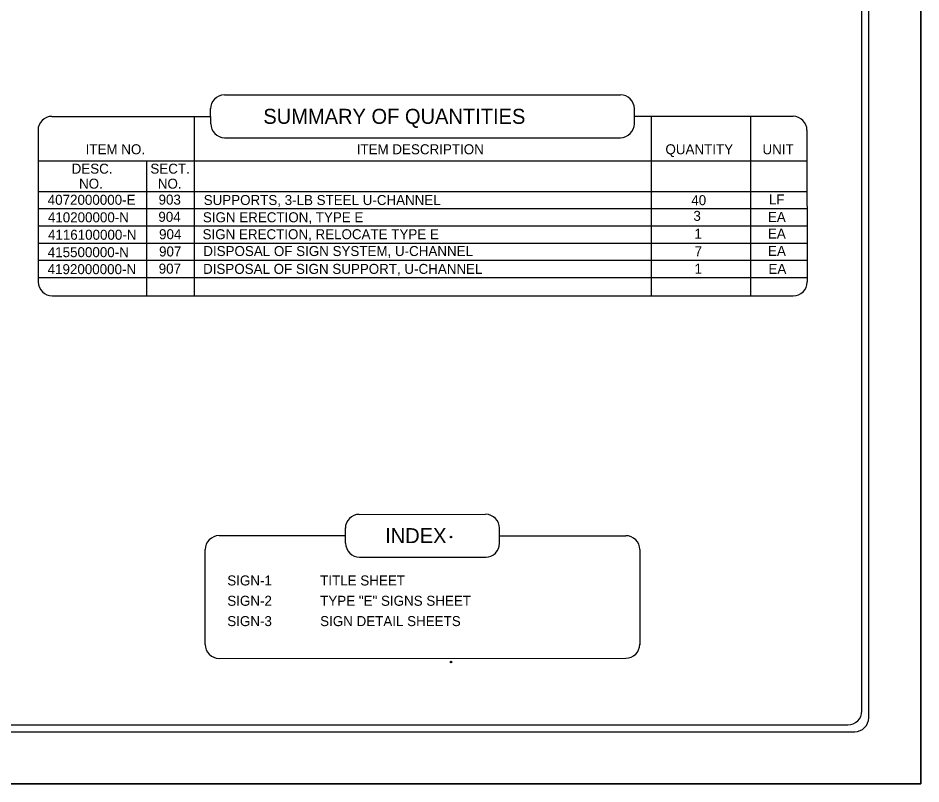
# Model space of a CAD drawing. Extents: x 1359317 to 1361345, y 1001522 to 1002524.
# Drawn here: x 1360274 to 1360865, y 1001522 to 1002023 of the extents above; entities that cross this region are included whole.
import ezdxf

# ---------------------------------------------------------------- set-up
doc = ezdxf.new("R2010")
doc.units = 0
for name, color, linetype in [('Default', 7, 'Continuous'), ('Draft_Construction', 7, 'Continuous'), ('Sheet Plot Border Outside CELL', 7, 'Continuous'), ('Sheet_Title_CELL', 7, 'Continuous'), ('Text', 7, 'Continuous'), ('z - Construction', 7, 'Continuous')]:
    doc.layers.add(name, color=color, linetype=linetype)

msp = doc.modelspace()

# ---------------------------------------------------------------- linework, layer by layer
at = {"layer": 'Default'}
for p, q in [((1360389.57, 1001958.51), (1360389.57, 1001841.1)), ((1360688.47, 1001958.52), (1360688.47, 1001841.09)), ((1360753.47, 1001958.52), (1360753.47, 1001841.09)), ((1360753.47, 1001949.44), (1360753.47, 1001929.44)), ((1360287.54, 1001929.38), (1360790.47, 1001929.45)), ((1360358.55, 1001929.39), (1360358.55, 1001841.11)), ((1360753.47, 1001929.44), (1360790.47, 1001929.45)), ((1360287.57, 1001909.39), (1360790.48, 1001909.39)), ((1360287.57, 1001898.15), (1360790.48, 1001898.15)), ((1360287.57, 1001886.91), (1360790.48, 1001886.91)), ((1360287.57, 1001875.66), (1360790.48, 1001875.66)), ((1360287.57, 1001864.42), (1360790.48, 1001864.42)), ((1360287.57, 1001853.17), (1360790.48, 1001853.17))]:
    msp.add_line(p, q, dxfattribs=at)
at = {"layer": 'Draft_Construction'}
for centre in [(1360557.61, 1001683.35), (1360557.61, 1001601.63)]:
    msp.add_circle(centre, 0.546, dxfattribs=at)
at = {"layer": 'Sheet Plot Border Outside CELL'}
msp.add_lwpolyline([(1359316.74, 1002523.7), (1360865.01, 1002523.7), (1360865.01, 1001521.88), (1359316.74, 1001521.88)], close=True, dxfattribs=at)
at = {"layer": 'Sheet_Title_CELL'}
for p, q in [((1360826.3, 1001569.62), (1360826.3, 1002475.82)), ((1360830.86, 1001565.14), (1360830.86, 1002480.44)), ((1360409.38, 1001972.49), (1360668.47, 1001972.49)), ((1360400.48, 1001953.64), (1360400.29, 1001963.62)), ((1360677.56, 1001953.63), (1360677.56, 1001963.4)), ((1360296.59, 1001958.51), (1360400.39, 1001958.51)), ((1360677.56, 1001958.52), (1360781.36, 1001958.52)), ((1360287.5, 1001949.41), (1360287.68, 1001850.2)), ((1360790.45, 1001949.43), (1360790.55, 1001850.18)), ((1360409.57, 1001944.55), (1360668.47, 1001944.54)), ((1360296.77, 1001841.11), (1360781.46, 1001841.09)), ((1360497.6, 1001698.18), (1360580.25, 1001698.22)), ((1360488.7, 1001679.33), (1360488.51, 1001689.31)), ((1360405.95, 1001684.28), (1360488.6, 1001684.32)), ((1360589.34, 1001679.32), (1360589.34, 1001689.09)), ((1360589.34, 1001684.21), (1360672, 1001684.25)), ((1360396.86, 1001613.08), (1360396.86, 1001675.19)), ((1360681.09, 1001675.16), (1360681.07, 1001612.85)), ((1360497.79, 1001670.24), (1360580.58, 1001670.24)), ((1360405.95, 1001603.99), (1360671.99, 1001604.13)), ((1359409.65, 1001560.53), (1360817.19, 1001560.53)), ((1359360, 1001556.03), (1360821.75, 1001556.03))]:
    msp.add_line(p, q, dxfattribs=at)
for centre, radius, start, end in [((1360409.38, 1001963.4), 9.09, 90, 180), ((1360668.48, 1001963.44), 9.09, 0, 90), ((1360296.59, 1001949.41), 9.09, 90, 180), ((1360781.36, 1001949.43), 9.09, 0.00114, 90), ((1360409.57, 1001953.64), 9.09, 180, 269.99749), ((1360668.47, 1001953.63), 9.09, 270, 0), ((1360296.77, 1001850.2), 9.09, 180, 270), ((1360781.46, 1001850.18), 9.09, 270, 0), ((1360497.6, 1001689.09), 9.09, 90, 180), ((1360580.25, 1001689.13), 9.09, 0, 90), ((1360405.95, 1001675.19), 9.09, 90, 180), ((1360672, 1001675.16), 9.09, 0, 90), ((1360497.79, 1001679.33), 9.09, 180, 269.99749), ((1360580.25, 1001679.32), 9.09, 270, 0), ((1360405.95, 1001613.08), 9.09, 180, 270), ((1360671.99, 1001613.22), 9.09, 270, 0), ((1360817.19, 1001569.64), 9.11, 270, 360), ((1360821.75, 1001565.14), 9.11, 270, 0)]:
    msp.add_arc(centre, radius, start, end, dxfattribs=at)
at = {"layer": 'z - Construction'}
for p, q in [((1360865.01, 1001521.88), (1360865.01, 1002523.7)), ((1359316.74, 1001521.88), (1360865.01, 1001521.88))]:
    msp.add_line(p, q, dxfattribs=at)

# ---------------------------------------------------------------- texts
at = {"layer": 'Text'}
for s, height, p in [('SUMMARY OF QUANTITIES', 9.8184, (1360434.86, 1001953.6)), ('INDEX', 9.818, (1360514.53, 1001679.36))]:
    msp.add_text(s, height=height, dxfattribs=at).set_placement(p)
for s, height, p in [('ITEM NO.', 6.546, (1360318.62, 1001933.7)), ('ITEM DESCRIPTION', 6.5456, (1360495.95, 1001933.7)), ('QUANTITY', 6.546, (1360697.89, 1001933.7)), ('UNIT', 6.546, (1360761.38, 1001933.7)), ('DESC.', 6.546, (1360309.48, 1001921.02)), ('SECT.', 6.546, (1360360.99, 1001921.02)), ('  NO.', 6.546, (1360309.48, 1001911.2)), ('  NO.', 6.546, (1360360.99, 1001911.2)), ('4072000000-E', 6.54, (1360293.86, 1001900.65)), ('903', 6.54, (1360366.34, 1001900.77)), ('SUPPORTS, 3-LB STEEL U-CHANNEL', 6.54, (1360395.88, 1001900.51)), ('40', 6.54, (1360714.81, 1001900.41)), ('LF', 6.54, (1360765.55, 1001900.87)), ('904', 6.54, (1360366.22, 1001889.52)), ('3', 6.54, (1360716.17, 1001890.14)), ('EA', 6.54, (1360764.9, 1001889.41)), ('410200000-N', 6.54, (1360293.95, 1001889.21)), ('SIGN ERECTION, TYPE E', 6.54, (1360395.33, 1001889.23)), ('4116100000-N', 6.54, (1360294, 1001877.79)), ('904', 6.54, (1360366.68, 1001878.16)), ('SIGN ERECTION, RELOCATE TYPE E', 6.54, (1360395.14, 1001878.14)), ('1', 6.54, (1360716.83, 1001878.5)), ('EA', 6.54, (1360764.9, 1001878.59)), ('415500000-N', 6.54, (1360293.88, 1001866.4)), ('907', 6.54, (1360366.67, 1001866.88)), ('DISPOSAL OF SIGN SYSTEM, U-CHANNEL', 6.54, (1360395.6, 1001867.14)), ('7', 6.54, (1360717.02, 1001867.04)), ('EA', 6.54, (1360765, 1001867.23)), ('4192000000-N', 6.54, (1360293.79, 1001855.3)), ('907', 6.54, (1360366.44, 1001855.65)), ('DISPOSAL OF SIGN SUPPORT, U-CHANNEL', 6.54, (1360395.46, 1001855.47)), ('1', 6.54, (1360716.92, 1001855.59)), ('EA', 6.54, (1360765.27, 1001855.49)), ('SIGN-1', 6.546, (1360411.29, 1001651.68)), ('TITLE SHEET', 6.5456, (1360472.05, 1001651.68)), ('SIGN-2', 6.546, (1360411.29, 1001638.39)), ('TYPE "E" SIGNS SHEET', 6.5456, (1360472.05, 1001638.39)), ('SIGN-3', 6.546, (1360411.29, 1001625.1)), ('SIGN DETAIL SHEETS', 6.5456, (1360472.05, 1001625.1))]:
    msp.add_text(s, height=height, rotation=359.99749, dxfattribs=at).set_placement(p)

doc.saveas('drawing.dxf')
